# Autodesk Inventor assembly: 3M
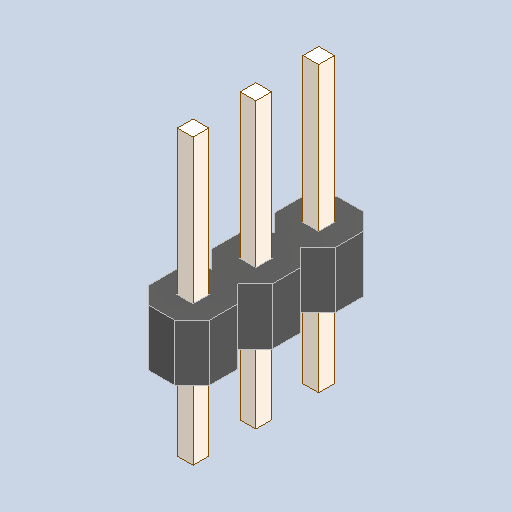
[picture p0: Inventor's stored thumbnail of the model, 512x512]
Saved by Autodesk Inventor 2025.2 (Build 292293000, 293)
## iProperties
Created: 2025-04
Part Number: 3M
Description: PART--DESC
Document SubType Name: Assembly
Designer: BennF
Author: BennF
Revision Number: NONE
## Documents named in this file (3)
- C:\Users\BennF\Nextcloud\Benutzer\CNC JarBeRi\existing parts\Electronics\RepRap A4988 Shied (USE WITHOUT ARDUINO)\reprap-a4988-1.snapshot.1\RepRap\RepRap\3M.iam
- C:\Users\BennF\Nextcloud\Benutzer\CNC JarBeRi\existing parts\Electronics\RepRap A4988 Shied (USE WITHOUT ARDUINO)\reprap-a4988-1.snapshot.1\RepRap\RepRap\3M Geometry.ipt
- C:\Users\BennF\Nextcloud\Benutzer\CNC JarBeRi\existing parts\Electronics\RepRap A4988 Shied (USE WITHOUT ARDUINO)\reprap-a4988-1.snapshot.1\RepRap\RepRap\Pin13.ipt
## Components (2 placed, 2 different names)
1. 3M Geometry
2. Pin13
